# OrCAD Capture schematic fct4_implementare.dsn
size A
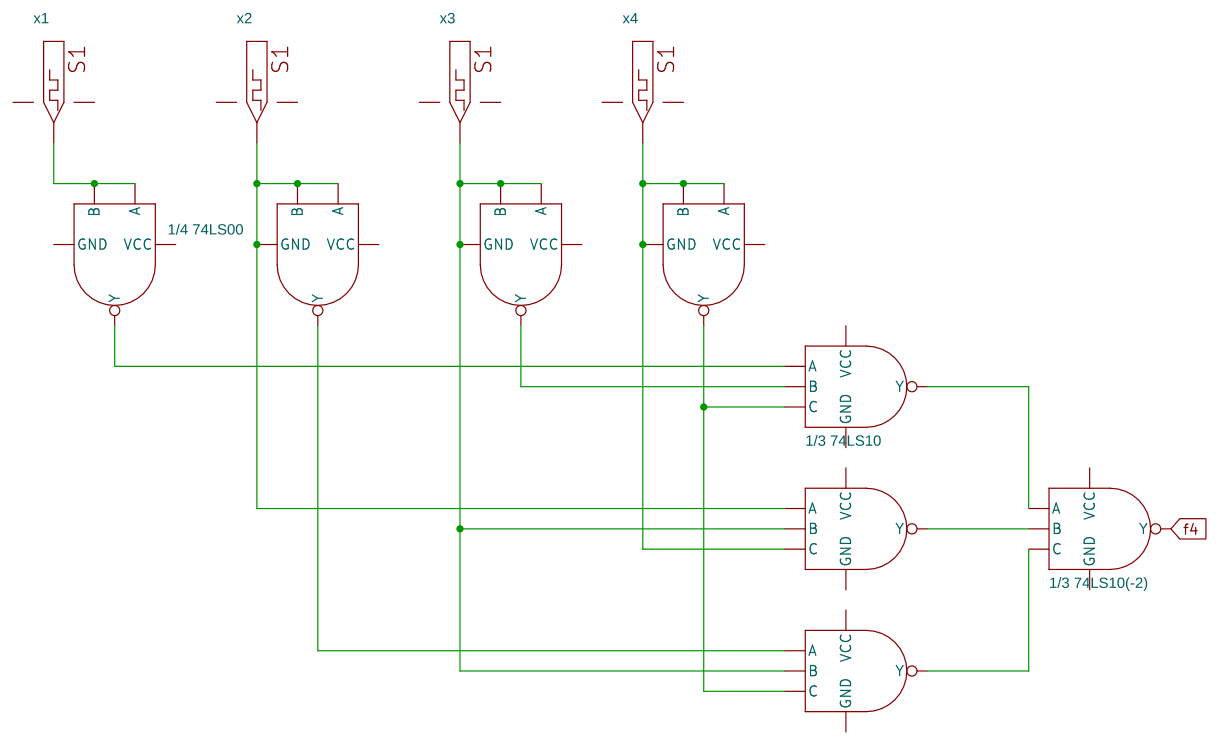
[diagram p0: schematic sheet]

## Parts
U4  1/4 74LS00  [DIP.100/14/W.300/L.800]  (sections A,B,C,D)
U5  1/4 74LS00  [DIP.100/14/W.300/L.800]  (section A)
U6  1/3 74LS10  [DIP.100/14/W.300/L.800]  (section B)
U7  1/3 74LS10  [DIP.100/14/W.300/L.800]  (section B)
U8  1/3 74LS10(-2)  [DIP.100/14/W.300/L.800]  (section B)
x1  DigStim1
x2  DigStim1
x3  DigStim1
x4  DigStim1

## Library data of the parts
U4 U5 = 74LS00
U6-U8 = 74LS10
x1-x4 = DigStim1

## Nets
GND: U4.7(GND) U5.7(GND) U6.7(GND) U7.7(GND) U8.7(GND) x1.3(GND) x2.3(GND) x3.3(GND) x4.3(GND)
VCC: U4.14(VCC) U5.14(VCC) U6.14(VCC) U7.14(VCC) U8.14(VCC) x1.2(VCC) x2.2(VCC) x3.2(VCC) x4.2(VCC)
f4: U8.6(Y)
N15903: U4.12(A) U4.13(B) U6.4(B) U7.4(B) x3.OUT
N15917: U5.1(A) U5.2(B) U6.5(C) x4.OUT
N15929: U4.9(A) U4.10(B) U6.3(A) x2.OUT
N15941: U4.1(A) U4.2(B) x1.OUT
N16161: U7.6(Y) U8.5(C)
N16174: U4.6(Y) U8.3(A)
N16181: U6.6(Y) U8.4(B)
N16192: U4.4(B) U4.11(Y)
N16199: U4.5(C) U5.3(Y) U7.5(C)
N16242: U4.8(Y) U7.3(A)

Not connected (* = marked no-connect by the designer): U4 3(A)
